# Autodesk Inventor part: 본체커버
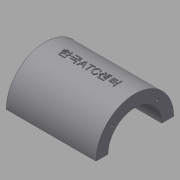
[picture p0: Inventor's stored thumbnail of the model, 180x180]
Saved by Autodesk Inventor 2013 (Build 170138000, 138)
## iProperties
Created: 2015-12
Part Number: 본체커버
Material: 일반
Document SubType Name: Modeling
Designer: mduedu
Density: 1 g/cm^3
Mass: 64.5736 g
Surface Area: 167.085 cm^2
Volume: 64.5736 cm^3
Author: mduedu
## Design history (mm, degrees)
sketch "스케치1"
  geometry: L1 (45, 40)-(-45, 40); L2 (-45, 40)-(-45, -40); L3 (-45, -40)-(45, -40); L4 (45, -40)-(45, 40); L5 (45, 40)-(-45, -40); L6 (-45, 40)-(45, -40); 1 further point
  constraints: 12 end point, 2 midpoint, 2 parallel, 1 horizontal, 1 perpendicular
  dimensions: "d0" = 90 distance of L2.end L3.end; "d2" = 80 distance of L1.end L2.end
extrude "돌출1" new body sketch "스케치1" distance "d3" = 10; taper "d4" = 0 deg
sketch "스케치2"
  geometry: L1 (0, 40)-(0, -40) reference; C1 r 32.5 at (80, 0); 1 further point
  constraints: 1 centre point
  dimensions: "d5" = 65 diameter of C1; "d6" = 80 distance from line of C1.centre L1
extrude "돌출2" join sketch "스케치2" stored distance "d7" = 75; taper "d8" = 0 deg
sketch "스케치3"
  geometry: L1 (-27.5, -20)-(27.5, -20); L2 (27.5, -20)-(27.5, 20); L3 (27.5, 20)-(-27.5, 20); L4 (-27.5, 20)-(-27.5, -20); L5 (-27.5, -20)-(27.5, 20); L6 (27.5, -20)-(-27.5, 20); 1 further point
  constraints: 12 end point, 2 midpoint, 2 parallel, 1 horizontal, 1 perpendicular
  dimensions: "d9" = 55 distance of L2.end L3.end; "d11" = 40 distance of L1.end L2.end
extrude "돌출3" new body sketch "스케치3" stored distance "d12" = 75; taper "d13" = 0 deg
fillet "모깎기1"
fillet "모깎기2"
feature "결합1"
  node "솔리드2"
fillet "모깎기3" dims "d14" = 10
sketch "스케치4"
  geometry: L1 (-37.5, 47.5)-(37.5, 47.5) reference; L2 (35, 10)-(45, 10) reference; L3 (32.5, 47.5)-(40, 10); L4 (37.5, 47.5)-(37.5, 112.5) reference; L5 (45, 10)-(45, 0) reference; 1 further point
  constraints: 2 end point, 1 midpoint, 1 point on line
  dimensions: "d15" = 5 distance from line of L3.start L4; "d16" = 5 distance from line of L3.end L5
sketch "스케치5"
  geometry: L1 (10, 40)-(10, 30) reference; L2 (10, 35)-(56.569, 22.522); L3 (0, 40)-(10, 40) reference; 2 further points
  constraints: 2 end point, 1 midpoint, 2 other
  dimensions: "d17" = 5 distance from line of L2.start L3; "d18" = 15 deg angle of L2 L3
feature "리브1" dims "d19" = 1, "d20" = 6, "d21" = 0, "d22" = 0, "d23" = 1, "d24" = 1
feature "리브2" dims "d25" = 1, "d26" = 6, "d27" = 0, "d28" = 0, "d29" = 1, "d30" = 1
fillet "모깎기4" dims "d31" = 2
fillet "모깎기5" dims "d32" = 2
fillet "모깎기6" dims "d33" = 2
sketch "스케치6"
  geometry: A1 r 10 centre (-35, 30) between (-35, 40) and (-45, 30) reference; A2 r 10 centre (35, 30) between (45, 30) and (35, 40) reference; A3 r 10 centre (35, -30) between (35, -40) and (45, -30) reference; A4 r 10 centre (-35, -30) between (-45, -30) and (-35, -40) reference; 5 further points
  constraints: 4 coincident
hole "구멍1" sketch "스케치6" at (-35, 30), (35, 30), (35, -30), (-35, -30) diameter "d34" = 7; stored, may be unused: countersink angle "d38" = 90 deg, drill point angle "d40" = 118 deg; dims "d35" = 6, "d36" = 12, "d37" = 3, "d39" = 8
fillet "모깎기7" dims "d41" = 2
hole "구멍2" diameter "d44" = 45; stored, may be unused: countersink angle "d48" = 90 deg, drill point angle "d50" = 118 deg; dims "d42" = 10, "d43" = 10, "d45" = 6, "d46" = 4, "d47" = 2, "d49" = 8
sketch "스케치7" dims "d52" = 26.5
  geometry: L1 (0, 0)-(32.5, 0); L2 (0, 0)-(22.981, 22.981); A1 r 32.5 centre (0, 0) between (32.5, 0) and (22.981, 22.981) reference; 3 further points
  constraints: 4 end point, 2 point on circle, 1 coincident, 1 horizontal, 1 point on line, 3 other
  dimensions: "d51" = 45 deg angle of L2 L1
hole "구멍3" sketch "스케치7" at (18.738, 18.738) diameter "d54" = 2.459; stored, may be unused: countersink angle "d58" = 90 deg, drill point angle "d60" = 118 deg; dims "d55" = 8, "d56" = 4, "d57" = 2, "d59" = 10
sketch "스케치13"
  geometry: L1 (-45, 80)-(105, 80); L2 (105, 80)-(105, -30); L3 (105, -30)-(-45, -30); L4 (-45, -30)-(-45, 80); L5 (0, 0)-(60, 0) reference; C1 r 32.5 at (30, 80) reference; 1 further point
  constraints: 8 end point, 2 parallel, 1 coincident, 1 horizontal, 1 midpoint, 1 perpendicular
  dimensions: "d99" = 30 distance between parallel lines of L3 L5; "d126" = 150 distance between parallel lines of L2 L4
extrude "돌출8" cut sketch "스케치13" stored distance "d97" = 10; taper "d98" = 0 deg
node "작업 평면2"
sketch "스케치14"
  geometry: 2 further points
  constraints: 1 coincident, 1 other
feature "엠보싱1" sketch "스케치14" dims "d102" = 0.5, "d103" = 0
sketch "스케치18"
  geometry: L1 (0, -10)-(0, 0) reference; L2 (75, 0)-(75, -10) reference; L3 (0, -5)-(75, -5); C1 r 1.5 at (13, -5); 1 further point
  constraints: 2 end point, 2 midpoint, 1 centre point, 1 point on line
  dimensions: "d127" = 3 diameter of C1; "d128" = 13 distance from line of L1 C1.centre
extrude "돌출9" cut sketch "스케치18" distance "d129" = 2; taper "d130" = 0 deg
chamfer "모따기2" distance "d131" = 0.5; stored, may be unused: second distance "d132" = 2, angle "d133" = 45 deg
fillet "모깎기12" dims "d134" = 0.1
node "솔리드1"
mirror "대칭1"
mirror "대칭2"
pattern_circular "원형 패턴1" dims angle "d62" = 360 deg
mirror "대칭3"
mirror "대칭5"
mirror "대칭6"
